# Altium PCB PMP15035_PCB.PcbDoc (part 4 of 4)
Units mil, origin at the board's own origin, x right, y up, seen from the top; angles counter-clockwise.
Board outline 5645 x 4585 mil, 8 copper layers (Top Layer, Signal Layer 1, Signal Layer 2, Signal Layer 3, Signal Layer 4, Signal Layer 5, Signal Layer 6, Bottom Layer), stack 60.9 mil thick; 335 components, 164 nets, 981 pads, 1349 vias.
Unrouted connection lines stored in the file: 46.
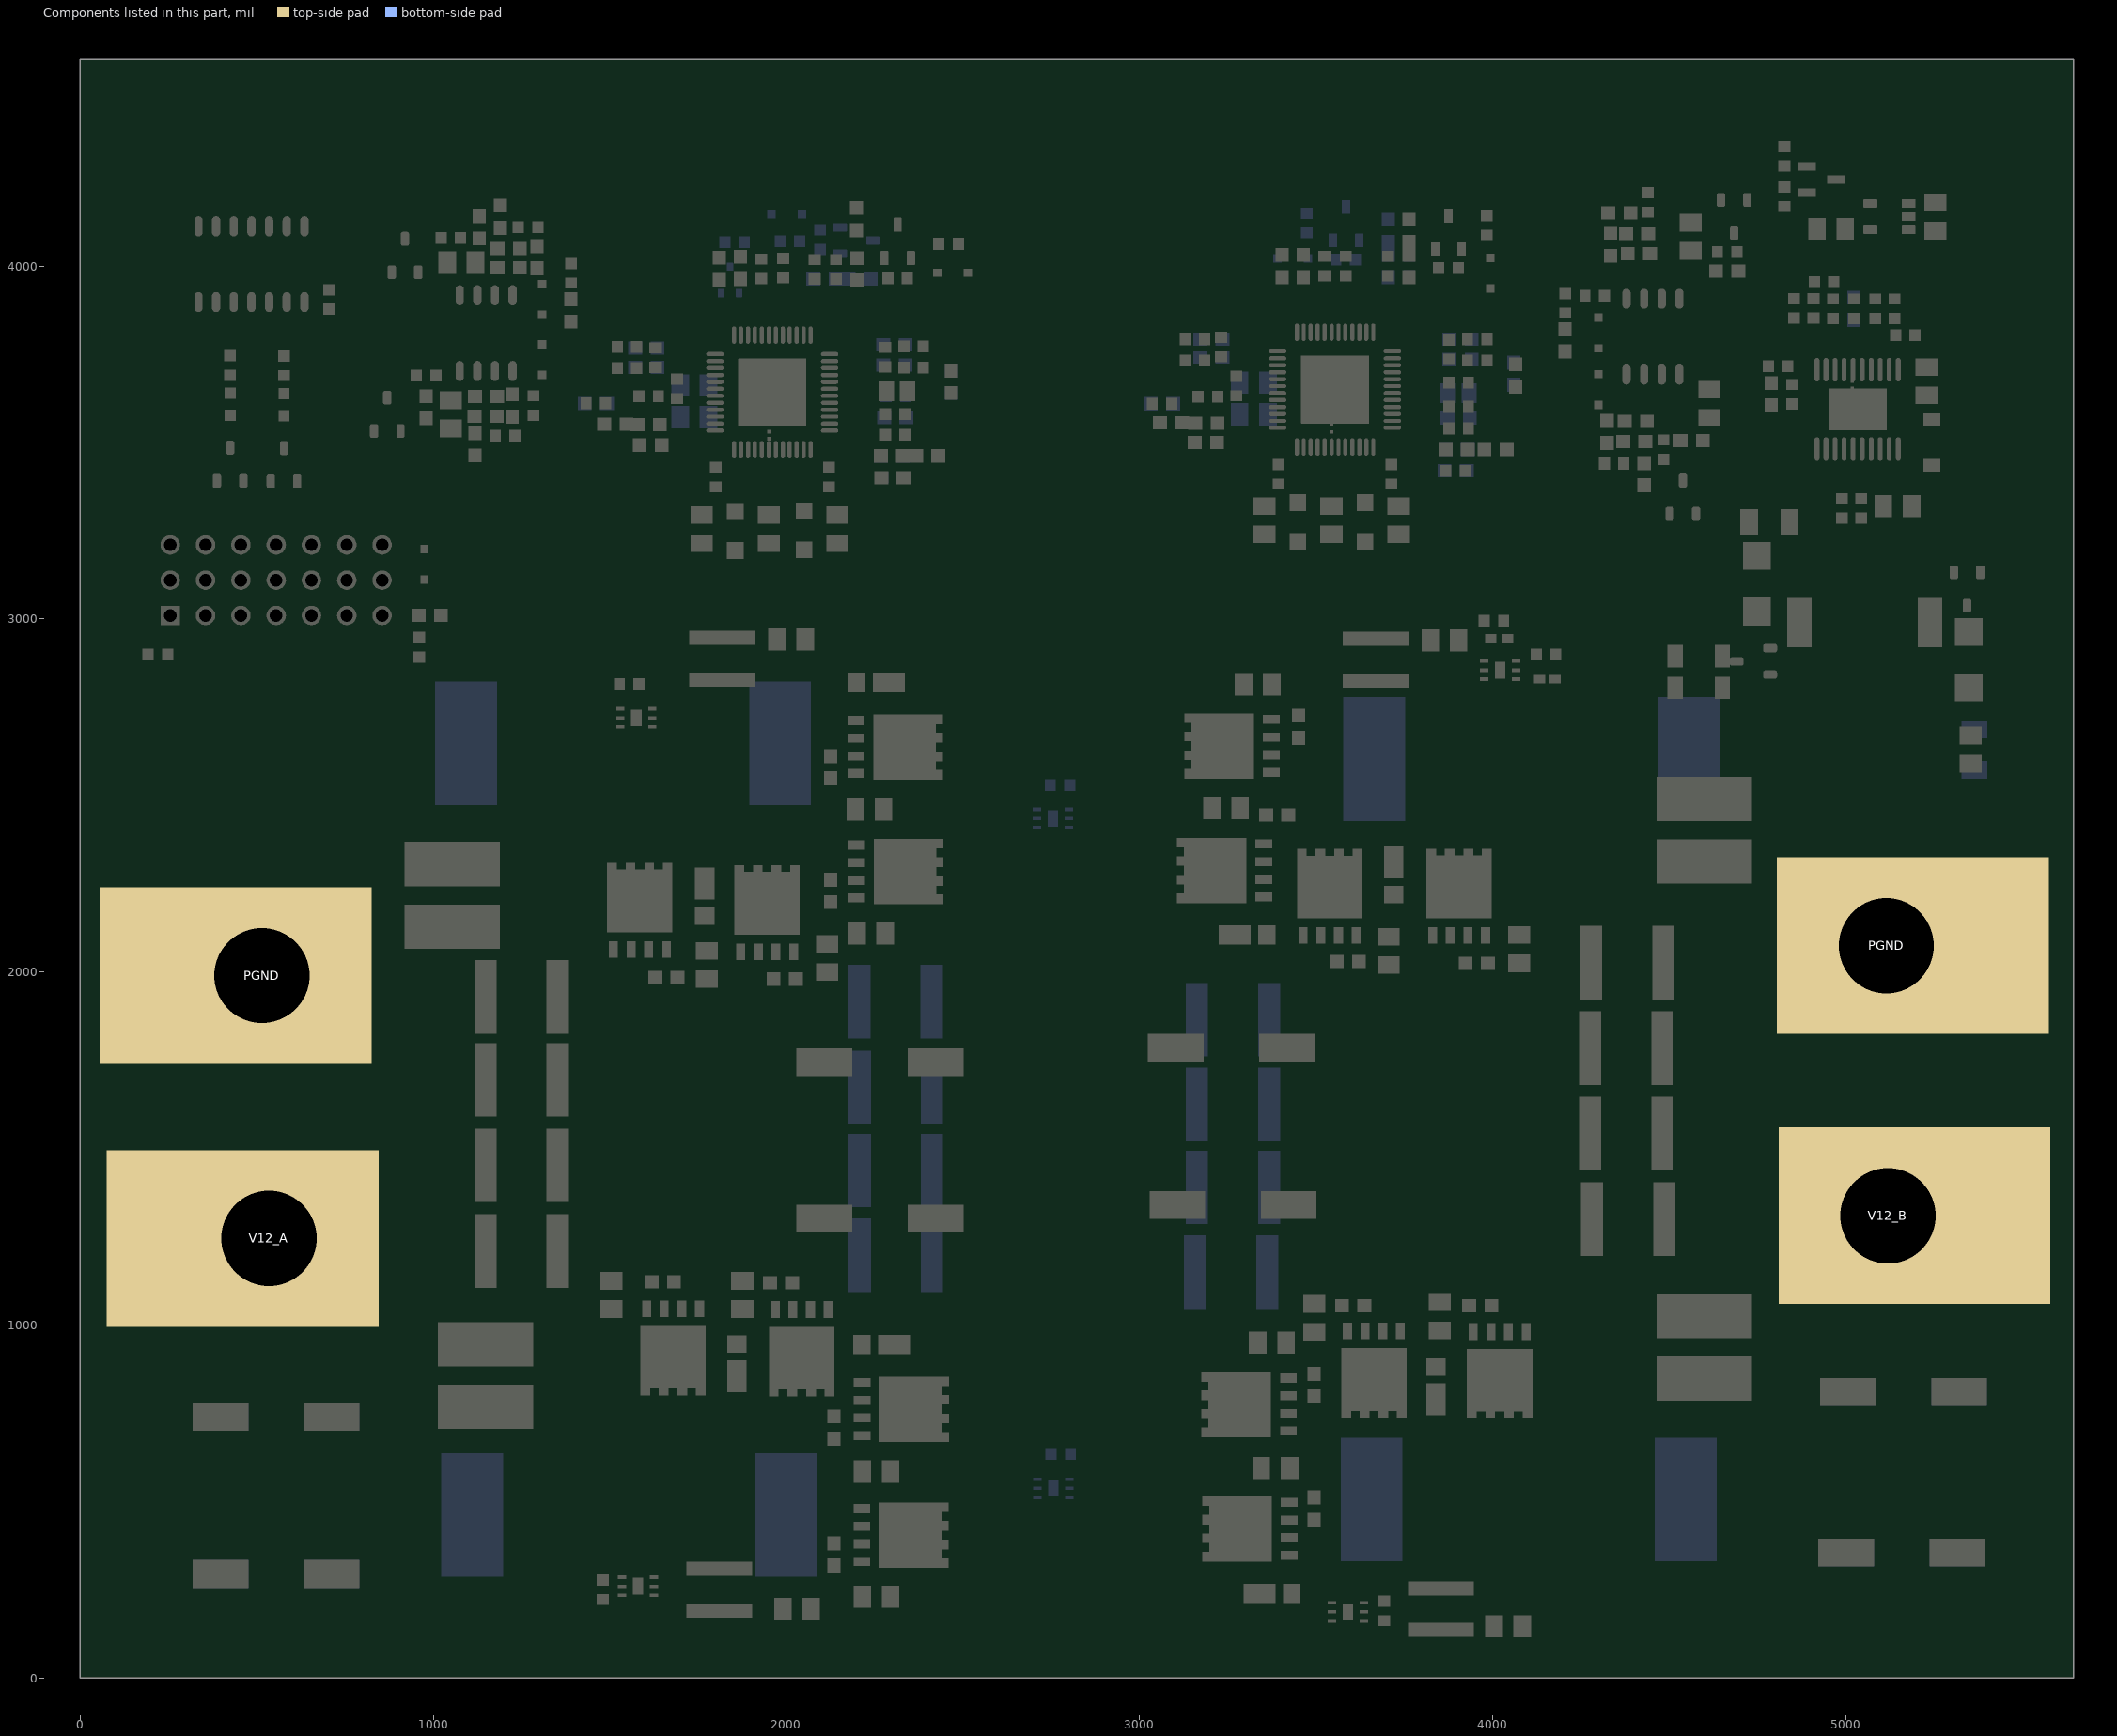
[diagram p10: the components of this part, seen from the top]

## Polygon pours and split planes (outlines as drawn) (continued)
NetL10_2 on Bottom Layer "BOTTOM_LAYER_NETL10_2_P1039" (solid, remove dead copper, pour order 1039): 19 vertices, not listed, extent 4129.88,2410 4739.88,3013.71
NetL11_1 on Bottom Layer "BOTTOM_LAYER_NETL11_1_P1040" (solid, remove dead copper, pour order 1040): 18 vertices, not listed, extent 4127.5,332.5 4745.26,915
NetL9_2 on Bottom Layer "BOTTOM_LAYER_NETL9_2_P1041" (solid, remove dead copper, pour order 1041): 17 vertices, not listed, extent 970,115 1520,718.52
AGND on Bottom Layer "BOTTOM_LAYER_AGND_P022" (solid, remove dead copper, pour order 1036): 2663.26,2583.41 2683.26,2603.41 2829.99,2603.41 2843.26,2590.15 2843.26,2398.26 2828.41,2383.41 2683.26,2383.41 2663.26,2403.41
SW11 on Bottom Layer "BOTTOM_LAYER_SW11_P1046" (solid, remove dead copper, pour order 1046): 25 vertices, not listed, extent 1493.19,2100 2225,2870
SW22 on Bottom Layer "Top Layer-SW226" (solid, remove dead copper, pour order 1043): 46 vertices, not listed, extent 3392.51,210 4115,938.8
SW21 on Bottom Layer "Top Layer-SW216" (solid, remove dead copper, pour order 1044): 28 vertices, not listed, extent 1585,285 2240,1000
SW12 on Bottom Layer "BOTTOM_LAYER_SW12_P1045" (solid, remove dead copper, pour order 1045): 31 vertices, not listed, extent 3325,2070 4005,2849.3
PGND on Top Layer "TOP_LAYER_PGND_P972" (solid, remove dead copper, pour order 972): 5641.25,2.5 5641.25,3706.49 5622.26,3687.5 -2.5,3687.5 -2.5,7.5 5636.25,7.5
AGND on Top Layer "Signal Layer 6-AGND" (solid, remove dead copper, pour order 971): 3364,3534 3706,3534 4090,3150 4495,3150 4940,3665 5643.75,3665 5643.75,4585 0,4585 0,2860 1120,2860 1790,3530 2095,3530 2430,3195 3025,3195
PGND on Top Layer "TOP_LAYER_PGND_P956" (solid, remove dead copper, pour order 956): 5390,310 5235,310 5225,320 5225,480 5260,515 5385,515 5410,490 5410,324.29
PGND on Top Layer "TOP_LAYER_PGND_P955" (solid, remove dead copper, pour order 955): 5245,855 5400,855 5410,845 5410,695 5378.85,663.85 5246.15,663.85 5225,685 5225,840.71
Vmid on Top Layer "Top Layer-Vmid1" (solid, remove dead copper, pour order 970): 3325,911.7 3385,851.7 3385,220 3360,195 2410,195 2235,370 2235,2848.39 2251.61,2865 3200,2865 3325,2740
V12_A on Top Layer "TOP_LAYER_V12_A_P968" (solid, remove dead copper, pour order 968): 1269.68,2130.31 1205,2195 910,2195 870.17,2155.17 870.17,2070 80,2070 80,340 205,215 230,215 390,215 770,215 830,275 830,785 935,890 1269.68,890
PGND on Top Layer "TOP_LAYER_PGND_P949" (solid, remove dead copper, pour order 949): 325,250 310,265 310,410 336.56,436.56 463.44,436.56 485,415 485,265 470,250
PGND on Top Layer "TOP_LAYER_PGND_P950" (solid, remove dead copper, pour order 950): 470,790 485,775 485,630 458.44,603.44 331.56,603.44 310,625 310,775 325,790
PGND on Top Layer "TOP_LAYER_PGND_P948" (solid, remove dead copper, pour order 948): 5245,313.44 5230,328.44 5230,473.44 5256.56,500 5383.44,500 5405,478.44 5405,328.44 5390,313.44
PGND on Top Layer "TOP_LAYER_PGND_P951" (solid, remove dead copper, pour order 951): 5390,865 5405,850 5405,705 5378.44,678.44 5251.56,678.44 5230,700 5230,850 5245,865
SW22 on Top Layer "TOP_LAYER_SW22_P214" (solid, remove dead copper, pour order 964): 46 vertices, not listed, extent 3392.51,210 4115,938.8
SW21 on Top Layer "TOP_LAYER_SW21_P034" (solid, remove dead copper, pour order 965): 28 vertices, not listed, extent 1585,285 2240,1000
AGND on Top Layer "TOP_LAYER_AGND_P028" (solid, remove dead copper, pour order 959): 3968.55,3043.55 4206.16,3043.55 4226.16,3023.55 4226.16,2852.57 4177.14,2803.55 3961.87,2803.55 3950,2815.41 3950,3025
AGND on Top Layer "TOP_LAYER_AGND_P026" (solid, remove dead copper, pour order 952): 1515,2855 1630,2855 1655,2830 1655,2675 1630,2650 1510,2650 1490,2670 1490,2830
AGND on Top Layer "TOP_LAYER_AGND_P020" (solid, remove dead copper, pour order 954): 1484.11,315 1670,315 1690,295 1690,190 1670,170 1475,170 1445,200 1445,282.41
AGND on Top Layer "TOP_LAYER_AGND_P018" (solid, remove dead copper, pour order 947): 3535,255 3700,255 3725,230 3725,150 3690,115 3550,115 3510,155 3510,230
NetD8_2 on Top Layer "TOP_LAYER_NETD8_2_P004" (solid, remove dead copper, pour order 953): 5180,3065 5375,3065 5395,3045 5395,2925 5385,2915 5180,2915 5170,2925 5170,3055
NetC21_1 on Top Layer "TOP_LAYER_NETC21_1_P958" (solid, remove dead copper, pour order 958): 4700,3095 4710,3105 4910,3105 4945,3070 4945,2930 4900,2885 4770,2885 4700,2955
NetL9_2 on Top Layer "TOP_LAYER_NETL9_2_P961" (solid, remove dead copper, pour order 961): 1520,375 1435,290 1435,165 1390,120 1060,120 975,205 975,794.62 1020.86,832.84 1287.16,832.84 1295,825 1295,720 1402.23,612.76 1472.24,612.76 1520,565
NetL8_1 on Top Layer "TOP_LAYER_NETL8_1_P963" (solid, remove dead copper, pour order 963): 891.49,2269.85 918.19,2243.15 1159.91,2243.15 1228.28,2175 1430,2175 1515,2260 1515,2755 1435,2835 1023.32,2835 1000,2814.6 1000,2480 891.49,2371.49
SW11 on Top Layer "TOP_LAYER_SW11_P967" (solid, remove dead copper, pour order 967): 34 vertices, not listed, extent 1493.19,2100 2225,2870
NetL11_1 on Top Layer "TOP_LAYER_NETL11_1_P962" (solid, remove dead copper, pour order 962): 4150,705 4125,680 4125,660 4125,495 4305,315 4635,315 4745,425 4745,905 4735,915 4255,915 4220,880 4220,719.25 4209.11,705
NetL10_2 on Top Layer "TOP_LAYER_NETL10_2_P960" (solid, remove dead copper, pour order 960): 17 vertices, not listed, extent 4132.96,2431.35 4742.96,3005
SW12 on Top Layer "TOP_LAYER_SW12_P966" (solid, remove dead copper, pour order 966): 31 vertices, not listed, extent 3325,2070 4005,2849.3
V12_B on Top Layer "TOP_LAYER_V12_B_P969" (solid, remove dead copper, pour order 969): 4796.5,960 4776.5,980 4740,980 4740,960 4420,960 4420,2331.92 4461.66,2373.58 5613.91,2373.58 5613.91,755 5613.91,380 5483.91,250 4980,250 4858.91,371.09 4858.91,901.09 4800,960
VCC1 on Top Layer "TOP_LAYER_VCC1_P957" (solid, remove dead copper, pour order 957): 5314.3,2890 5400.89,2890 5430,2860.88 5430,2647.82 5401.45,2619.28 5310.07,2619.28 5279.85,2649.5 5279.85,2857.92
PGND on Signal Layer 2 "SIGNAL_LAYER_2_PGND_P991" (solid, remove dead copper, pour order 991): 5643.75,0 5643.75,3703.99 5624.76,3685 0,3685 0,5 5638.75,5
AGND on Signal Layer 2 "Signal Layer 6-AGND2" (solid, remove dead copper, pour order 990): 3364,3534 3706,3534 4090,3150 4495,3150 4940,3665 5643.75,3665 5643.75,4585 0,4585 0,2860 1120,2860 1790,3530 2095,3530 2430,3195 3025,3195
Vmid on Signal Layer 2 "Top Layer-Vmid" (solid, remove dead copper, pour order 989): 3325,911.7 3385,851.7 3385,220 3360,195 2410,195 2235,370 2235,2848.39 2251.61,2865 3200,2865 3325,2740
V12_A on Signal Layer 2 "SIGNAL_LAYER_2_V12_A_P987" (solid, remove dead copper, pour order 987): 1269.68,2130.31 1205,2195 910,2195 870.17,2155.17 870.17,2070 80,2070 80,340 205,215 230,215 390,215 770,215 830,275 830,725 990,885 1269.68,885
V12_B on Signal Layer 2 "SIGNAL_LAYER_2_V12_B_P988" (solid, remove dead copper, pour order 988): 5613.91,755 5613.91,380 5483.91,250 4980,250 4858.91,371.09 4858.91,880 4809.46,929.45 4455.55,929.45 4420,965 4420,2335 4485,2400 5613.91,2400
NetL11_1 on Signal Layer 2 "SIGNAL_LAYER_2_NETL11_1_P979" (solid, remove dead copper, pour order 979): 4727.67,769.28 4577.67,919.28 4257.67,919.28 4212.67,874.28 4212.67,549.28 4357.67,404.28 4472.67,404.28 4727.67,659.28
NetL10_2 on Signal Layer 2 "SIGNAL_LAYER_2_NETL10_2_P980" (solid, remove dead copper, pour order 980): 4730.39,2544.14 4660.39,2474.14 4350.39,2474.14 4174.45,2650.08 4174.45,2933.2 4255.39,3014.14 4468.25,3014.14 4730.39,2752
NetL9_2 on Signal Layer 2 "SIGNAL_LAYER_2_NETL9_2_P981" (solid, remove dead copper, pour order 981): 1180,725 975,520 975,495 975,200 1075,100 1380,100 1475.47,195.47 1475.47,606.25 1356.72,725
NetL8_1 on Signal Layer 2 "SIGNAL_LAYER_2_NETL8_1_P982" (solid, remove dead copper, pour order 982): 994.25,2360.75 1180,2175 1430,2175 1514.57,2259.57 1514.57,2755.43 1470,2800 1219.29,2800 994.25,2603.1
SW11 on Signal Layer 2 "SIGNAL_LAYER_2_SW11_P986" (solid, remove dead copper, pour order 986): 25 vertices, not listed, extent 1493.19,2100 2225,2870
SW22 on Signal Layer 2 "Top Layer-SW221" (solid, remove dead copper, pour order 983): 46 vertices, not listed, extent 3392.51,210 4115,938.8
SW21 on Signal Layer 2 "Top Layer-SW211" (solid, remove dead copper, pour order 984): 28 vertices, not listed, extent 1585,285 2240,1000
SW12 on Signal Layer 2 "SIGNAL_LAYER_2_SW12_P985" (solid, remove dead copper, pour order 985): 31 vertices, not listed, extent 3325,2070 4005,2849.3
PGND on Signal Layer 3 "SIGNAL_LAYER_3_PGND_P1004" (solid, remove dead copper, pour order 1004): 5643.75,0 5643.75,3703.99 5624.76,3685 0,3685 0,5 5638.75,5
AGND on Signal Layer 3 "Signal Layer 6-AGND3" (solid, remove dead copper, pour order 1003): 3364,3534 3706,3534 4090,3150 4495,3150 4940,3665 5643.75,3665 5643.75,4585 0,4585 0,2860 1120,2860 1790,3530 2095,3530 2430,3195 3025,3195
Vmid on Signal Layer 3 "Top Layer-Vmid2" (solid, remove dead copper, pour order 1002): 3325,911.7 3385,851.7 3385,220 3360,195 2410,195 2235,370 2235,2848.39 2251.61,2865 3200,2865 3325,2740
V12_A on Signal Layer 3 "SIGNAL_LAYER_3_V12_A_P1000" (solid, remove dead copper, pour order 1000): 1269.68,2130.31 1205,2195 910,2195 870.17,2155.17 870.17,2070 80,2070 80,340 205,215 230,215 390,215 770,215 830,275 830,725 990,885 1269.68,885
NetL8_1 on Signal Layer 3 "SIGNAL_LAYER_3_NETL8_1_P995" (solid, remove dead copper, pour order 995): 994.25,2360.75 1180,2175 1430,2175 1514.57,2259.57 1514.57,2755.43 1470,2800 1219.29,2800 994.25,2603.1
NetL11_1 on Signal Layer 3 "SIGNAL_LAYER_3_NETL11_1_P992" (solid, remove dead copper, pour order 992): 4735.39,769.14 4585.39,919.14 4265.39,919.14 4220.39,874.14 4220.39,549.14 4365.39,404.14 4480.39,404.14 4735.39,659.14
NetL9_2 on Signal Layer 3 "SIGNAL_LAYER_3_NETL9_2_P994" (solid, remove dead copper, pour order 994): 1180,725 975,520 975,495 975,200 1075,100 1380,100 1475.47,195.47 1475.47,604.53 1355,725
NetL10_2 on Signal Layer 3 "SIGNAL_LAYER_3_NETL10_2_P993" (solid, remove dead copper, pour order 993): 4740.39,2549.14 4670.39,2479.14 4360.39,2479.14 4184.45,2655.08 4184.45,2938.2 4265.39,3019.14 4478.25,3019.14 4740.39,2757
V12_B on Signal Layer 3 "SIGNAL_LAYER_3_V12_B_P1001" (solid, remove dead copper, pour order 1001): 5613.91,755 5613.91,380 5483.91,250 4980,250 4858.91,371.09 4858.91,880 4809.46,929.45 4455.55,929.45 4420,965 4420,2331.92 4488.08,2400 5613.91,2400
SW11 on Signal Layer 3 "SIGNAL_LAYER_3_SW11_P999" (solid, remove dead copper, pour order 999): 25 vertices, not listed, extent 1493.19,2100 2225,2870
SW22 on Signal Layer 3 "Top Layer-SW222" (solid, remove dead copper, pour order 996): 46 vertices, not listed, extent 3392.51,210 4115,938.8
SW21 on Signal Layer 3 "Top Layer-SW212" (solid, remove dead copper, pour order 997): 28 vertices, not listed, extent 1585,285 2240,1000
SW12 on Signal Layer 3 "SIGNAL_LAYER_3_SW12_P998" (solid, remove dead copper, pour order 998): 31 vertices, not listed, extent 3325,2070 4005,2849.3
PGND on Signal Layer 5 "SIGNAL_LAYER_5_PGND_P1023" (solid, remove dead copper, pour order 1023): 5643.75,0 5643.75,3703.99 5624.76,3685 0,3685 0,5 5638.75,5
AGND on Signal Layer 5 "Signal Layer 6-AGND5" (solid, remove dead copper, pour order 1022): 3364,3534 3706,3534 4090,3150 4495,3150 4940,3665 5643.75,3665 5643.75,4585 0,4585 0,2860 1120,2860 1790,3530 2095,3530 2430,3195 3025,3195
Vmid on Signal Layer 5 "Top Layer-Vmid3" (solid, remove dead copper, pour order 1021): 3325,911.7 3385,851.7 3385,220 3360,195 2410,195 2235,370 2235,2848.39 2251.61,2865 3200,2865 3325,2740
V12_A on Signal Layer 5 "SIGNAL_LAYER_5_V12_A_P1019" (solid, remove dead copper, pour order 1019): 1269.68,2130.31 1205,2195 910,2195 870.17,2155.17 870.17,2070 80,2070 80,340 205,215 230,215 390,215 770,215 830,275 830,725 990,885 1269.68,885
NetL8_1 on Signal Layer 5 "SIGNAL_LAYER_5_NETL8_1_P1014" (solid, remove dead copper, pour order 1014): 994.25,2360.75 1180,2175 1430,2175 1514.57,2259.57 1514.57,2755.43 1470,2800 1219.29,2800 994.25,2603.1
NetL11_1 on Signal Layer 5 "SIGNAL_LAYER_5_NETL11_1_P1011" (solid, remove dead copper, pour order 1011): 4730.39,770.86 4580.39,920.86 4260.39,920.86 4215.39,875.86 4215.39,550.86 4360.39,405.86 4475.39,405.86 4730.39,660.86
NetL9_2 on Signal Layer 5 "SIGNAL_LAYER_5_NETL9_2_P1013" (solid, remove dead copper, pour order 1013): 1180,725 975,520 975,495 975,200 1075,100 1380,100 1475.47,195.47 1475.47,618.95 1369.42,725
NetL10_2 on Signal Layer 5 "SIGNAL_LAYER_5_NETL10_2_P1012" (solid, remove dead copper, pour order 1012): 4744.07,2543.41 4674.07,2473.41 4364.07,2473.41 4188.14,2649.34 4188.14,2932.47 4269.07,3013.41 4481.94,3013.41 4744.07,2751.26
V12_B on Signal Layer 5 "SIGNAL_LAYER_5_V12_B_P1020" (solid, remove dead copper, pour order 1020): 5613.91,755 5613.91,380 5483.91,250 4980,250 4858.91,371.09 4858.91,880 4809.46,929.45 4455.55,929.45 4420,965 4420,2331.92 4488.08,2400 5613.91,2400
SW11 on Signal Layer 5 "SIGNAL_LAYER_5_SW11_P1018" (solid, remove dead copper, pour order 1018): 25 vertices, not listed, extent 1493.19,2100 2225,2870
SW22 on Signal Layer 5 "Top Layer-SW224" (solid, remove dead copper, pour order 1015): 46 vertices, not listed, extent 3392.51,210 4115,938.8
SW21 on Signal Layer 5 "Top Layer-SW214" (solid, remove dead copper, pour order 1016): 28 vertices, not listed, extent 1585,285 2240,1000
SW12 on Signal Layer 5 "SIGNAL_LAYER_5_SW12_P1017" (solid, remove dead copper, pour order 1017): 31 vertices, not listed, extent 3325,2070 4005,2849.3
PGND on Signal Layer 6 "SIGNAL_LAYER_6_PGND_P1029" (solid, remove dead copper, pour order 1029): 5643.75,0 5643.75,3703.99 5624.76,3685 0,3685 0,5 5638.75,5
AGND on Signal Layer 6 "Top Layer-AGND5" (solid, remove dead copper, pour order 1028): 3364,3534 3706,3534 4090,3150 4495,3150 4940,3665 5643.75,3665 5643.75,4585 0,4585 0,2860 1120,2860 1790,3530 2095,3530 2430,3195 3025,3195
SW11 on Signal Layer 6 "SIGNAL_LAYER_6_SW11_P1027" (solid, remove dead copper, pour order 1027): 25 vertices, not listed, extent 1493.19,2100 2225,2870
SW22 on Signal Layer 6 "Top Layer-SW225" (solid, remove dead copper, pour order 1024): 46 vertices, not listed, extent 3392.51,210 4115,938.8
SW21 on Signal Layer 6 "Top Layer-SW215" (solid, remove dead copper, pour order 1025): 28 vertices, not listed, extent 1585,285 2240,1000
SW12 on Signal Layer 6 "SIGNAL_LAYER_6_SW12_P1026" (solid, remove dead copper, pour order 1026): 31 vertices, not listed, extent 3325,2070 4005,2849.3
PGND on Signal Layer 1 "SIGNAL_LAYER_1_PGND_P978" (solid, remove dead copper, pour order 978): 5643.75,0 5643.75,3703.99 5624.76,3685 0,3685 0,5 5638.75,5
AGND on Signal Layer 1 "Signal Layer 6-AGND1" (solid, remove dead copper, pour order 977): 3364,3534 3706,3534 4090,3150 4495,3150 4940,3665 5643.75,3665 5643.75,4585 0,4585 0,2860 1120,2860 1790,3530 2095,3530 2430,3195 3025,3195
SW11 on Signal Layer 1 "SIGNAL_LAYER_1_SW11_P976" (solid, remove dead copper, pour order 976): 25 vertices, not listed, extent 1493.19,2100 2225,2870
SW22 on Signal Layer 1 "Top Layer-SW22" (solid, remove dead copper, pour order 973): 46 vertices, not listed, extent 3392.51,210 4115,938.8
SW21 on Signal Layer 1 "Top Layer-SW21" (solid, remove dead copper, pour order 974): 28 vertices, not listed, extent 1585,285 2240,1000
SW12 on Signal Layer 1 "SIGNAL_LAYER_1_SW12_P975" (solid, remove dead copper, pour order 975): 31 vertices, not listed, extent 3325,2070 4005,2849.3
PGND on Signal Layer 4 "SIGNAL_LAYER_4_PGND_P1010" (solid, remove dead copper, pour order 1010): 5643.75,0 5643.75,3703.99 5624.76,3685 0,3685 0,5 5638.75,5
AGND on Signal Layer 4 "Bottom Layer-AGND" (solid, remove dead copper, pour order 1009): 3364,3534 3706,3534 4090,3150 4495,3150 4940,3665 5643.75,3665 5643.75,4585 0,4585 0,2860 1120,2860 1790,3530 2095,3530 2430,3195 3025,3195
SW11 on Signal Layer 4 "SIGNAL_LAYER_4_SW11_P1008" (solid, remove dead copper, pour order 1008): 25 vertices, not listed, extent 1493.19,2100 2225,2870
SW22 on Signal Layer 4 "Top Layer-SW223" (solid, remove dead copper, pour order 1005): 46 vertices, not listed, extent 3392.51,210 4115,938.8
SW21 on Signal Layer 4 "Top Layer-SW213" (solid, remove dead copper, pour order 1006): 28 vertices, not listed, extent 1585,285 2240,1000
SW12 on Signal Layer 4 "SIGNAL_LAYER_4_SW12_P1007" (solid, remove dead copper, pour order 1007): 31 vertices, not listed, extent 3325,2070 4005,2849.3

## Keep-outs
Keep-Out Layer:
  the board outline again, w8
  text ".Layer_Name" at -1078,-1628.49 h40

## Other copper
Top Layer:
  pour cut-out: 3425.03,3764.47 3448.35,3787.8 3659.14,3787.8 3688.75,3758.19 3688.75,3523.38 3677.58,3512.2 3427.86,3512.2 3418.75,3521.32 3418.75,3756.41
  pour cut-out: 1822.66,3767.66 1835,3780 2074.33,3780 2092.39,3761.94 2092.39,3516.42 2080.68,3504.71 1836.23,3504.71 1822.66,3520 1822.66,3523.61
  pour cut-out: 4919.8,3670 5138.75,3670 5153.75,3655 5153.75,3525 5138.75,3510 4918.55,3510 4903.83,3524.73 4903.83,3657.14
  text ".Layer_Name" at -1078,-1628.49 h40
Signal Layer 1:
  text "'.Layer_Name'" at -1080,-1625 h72.83
Signal Layer 2:
  pour cut-out: 927.13,2200 927.13,823.13 967.13,863.13 967.13,2187.87 955,2200
  pour cut-out: 4748.32,955 4749.13,954.19 4749.13,930 4770.87,930 4770.87,955
  pour cut-out: 4485,1222.87 4485,1221.62 4778.19,928.43 4785,935.23 4785,965 4527.13,1222.87
  pour cut-out: 4511.94,1222.87 4485,1222.87 4485,2405 4511.94,2405
  pour cut-out: 4475,2470 4460,2470 4455,2475 4455,3021.55 4481.94,3021.55 4481.94,2476.94
  pour cut-out: 4473.45,2474.14 4473.45,3021.55 4470,3025 4468.25,3023.25 4468.25,2468.37 4468.75,2467.87 4468.75,2469.43
  text "'.Layer_Name'" at -1085,-1630 h72.83
Signal Layer 3:
  text "'.Layer_Name'" at -1075,-1635 h72.83
Signal Layer 4:
  text "'.Layer_Name'" at -1080,-1640 h72.83
Signal Layer 5:
  text "'.Layer_Name'" at -1080,-1645 h72.83
Signal Layer 6:
  text "'.Layer_Name'" at -1070,-1635 h72.83
Bottom Layer:
  text ".Layer_Name" at -1078,-1628.49 h40

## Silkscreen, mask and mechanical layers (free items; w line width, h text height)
Top Overlay:
  lines w7: 4390,3400 4397.63,3407.63 4397.63,3413.51 4397.63,3454.66 4400,3457.04 4400,3475 ; 4400,3475 4405,3470 4395,3470 4400,3475
  text "A to B" at 374.63,3270.37 h72.83
  text "LOW" at 35,3200 h72.83
  text "HIGH" at 35,2985 h72.83
  text "EN1" at 275,2760 h72.83 r90
  text "EN2" at 370,2755 h72.83 r90
  text "B to A" at 470,2755 h72.83 r90
  text "UVLO" at 890,2755 h72.83 r90
  text "SYNCIN" at 575,2700 h72.83 r90
  text ".Layer_Name" at -1078,-1628.49 h40
Bottom Overlay:
  text ".Layer_Name" at -1078,-1628.49 h40
Top Paste:
  text ".Layer_Name" at -1078,-1628.49 h40
Bottom Paste:
  text ".Layer_Name" at -1078,-1628.49 h40
Top Solder:
  text ".Layer_Name" at -1078,-1628.49 h40
  text ".Layer_Name" at -1078,-1628.49 h40
Bottom Solder:
  text ".Layer_Name" at -1078,-1628.49 h40
Drill Guide:
  text ".Layer_Name" at -1078,-1628.49 h40
M1 Board Outline:
  the board outline again, w10
  text ".Layer_Name" at -1078,-1628.49 h40
M2 Board Dimensions:
  lines w7: 0,-85 0,165 ; 5643.75,-190 5643.75,60
  text ".Layer_Name" at -1078,-1628.49 h40
M3 3D STEP Top:
  text ".Layer_Name" at -1078,-1628.49 h40
M4 3D STEP Bottom:
  text ".Layer_Name" at -1078,-1628.49 h40
M5 Assembly Top:
  lines w10: -1947,-1700.17 4653,-1700.17 ; -1947,-1496.83 4655,-1496.83 ; -1947,-1293.5 -1947,-1903.5 2058,-1903.5 4655,-1903.5 4655,-1293.5 -1946.5,-1293.5 -1946.5,-1903.5 -371,-1903.5 ; 518,-1903.5 518,-1293.5 ; 1785,-1496.83 1785,-1293.5 ; 2625,-1496.83 2625,-1293.5 ; 3247,-1910 3247,-1707.17
  text "COMPONENTS MARKED 'DNP' SHOULD NOT BE POPULATED." at 563.5,151.5 h40
  text "ASSEMBLY VARIANT:" at 563,36 h40
  text ".VariantName" at 1599,36 h40
  text "PCB VIEWED FROM TOP SIDE" at -1883.5,-1425.67 h40
  text "BOARD #:" at 593,-1425.67 h40
  text ".PRJ_Number" at 1138.5,-1425.67 h40
  text "REV:" at 1983,-1425.67 h40
  text ".PCB_Rev" at 2274.5,-1425.67 h40
  text "SVN REV:" at 2821,-1425.67 h40
  text ".VersionControl_RevNumber" at 3327,-1425.67 h40
  text "TID #:" at 593,-1629 h40
  text ".TID" at 1138.5,-1629 h40
  text "PLOT NAME =" at -1883.5,-1834.34 h40
  text ".plot_File_Name" at -1078,-1834.34 h40
  text "GENERATED    :" at 595,-1834.34 h40
  text ".Print_Date" at 1464.5,-1834.34 h40
  text ".Print_Time" at 2193.5,-1834.34 h40
  text "TEXAS INSTRUMENTS" at 3458,-1834.34 h40
M6 Assembly Bottom:
  lines w10: -1947.5,-1497.33 4654.5,-1497.33 ; -1945.5,-1700.67 4654.5,-1700.67 ; -539.5,-1910.5 -539.5,-1707.67 ; 82.5,-1497.33 82.5,-1294 ; 922.5,-1497.33 922.5,-1294 ; 2189.5,-1904 2189.5,-1294 ; 3078.5,-1904 4654,-1904 4654,-1294 -1947.5,-1294 -1947.5,-1904 649.5,-1904 4654.5,-1904 4654.5,-1294
  text "COMPONENTS MARKED 'DNP' SHOULD NOT BE POPULATED." at 5890.75,162 h40
  text ".VariantName" at 4846.75,46 h40
  text "ASSEMBLY VARIANT:" at 6300,-45 h40
  text ".VersionControl_RevNumber" at -619.5,-1426.17 h40
  text "SVN REV:" at -113.5,-1426.17 h40
  text ".PCB_Rev" at 433,-1426.17 h40
  text "REV:" at 724.5,-1426.17 h40
  text ".PRJ_Number" at 1569,-1426.17 h40
  text "BOARD #:" at 2114.5,-1426.17 h40
  text "PCB VIEWED FROM BOTTOM SIDE" at 4591,-1426.17 h40
  text ".TID" at 1569,-1629.5 h40
  text "TID #:" at 2114.5,-1629.5 h40
  text "TEXAS INSTRUMENTS" at -750.5,-1834.84 h40
  text ".Print_Time" at 514,-1834.84 h40
  text ".Print_Date" at 1243,-1834.84 h40
  text "GENERATED    :" at 2112.5,-1834.84 h40
  text ".plot_File_Name" at 3785.5,-1834.84 h40
  text "PLOT NAME =" at 4591,-1834.84 h40
M9 Title Sheet:
  drawing of 57 lines, arcs and shapes, not listed
  text "1" at -915.16,7266.5 h40
  text "2" at 1580.5,7266.5 h40
  text "3" at 4069.84,7266.5 h40
  text "4" at 6576.51,7266.5 h40
  text "5" at 9075.5,7266.5 h40
  text "6" at 11580.5,7266.5 h40
  text "A" at -2071.5,6123.5 h40
  text "A" at 12728.5,6123.5 h40
  text "B" at -2071.5,3743.5 h40
  text "B" at 12728.5,3743.5 h40
  text "C" at -2071.5,1368.5 h40
  text "C" at 12728.5,1368.5 h40
  text "PROJECT TITLE:" at 9688.5,-492.5 h40
  text ".PRJ_Title" at 9738.5,-625.83 h40
  text "DESIGNED FOR:" at 9688.5,-793.5 h40
  text ".PRJ_Customer" at 9738.5,-933.5 h40
  text "D" at -2071.5,-1001.5 h40
  text "D" at 12728.5,-1001.5 h40
  text "FILE NAME:" at 9688.5,-1093.5 h40
  text ".PCB_File_Name_No_Path" at 9738.5,-1213.5 h40
  text "Texas Instruments (TI) and/or its licensors do not warrant the accuracy or completeness of this specification" at 4719,-1375.34 h40
  text "ENGINEER:" at 9688.5,-1383.5 h40
  text "LAYOUT BY:" at 11193.5,-1383.5 h40
  text "or any information contained therein. TI and/or its licensors do not warrant that this design will meet" at 4674.01,-1488 h40
  text ".PRJ_Engineer" at 9738.5,-1538.49 h40
  text ".PCB_Layout" at 11244,-1538.49 h40
  text "the specifications, will be suitable for your application or fit for any particular purpose, or will operate in" at 4674.01,-1600.67 h40
  text ".Layer_Name" at -1078,-1628.49 h40
  text "ALTIUM DESIGNER VERSION:" at 11193.5,-1693.5 h40
  text "an implementation. TI and/or its licensors do not warrant that the design is production worthy. You should" at 4674.01,-1713.33 h40
  text "completely validate and test your design implementation to confirm the system functionality for your application." at 4719,-1826 h40
  text ".print_Scale" at 9738.5,-1826.83 h40
  text ".Application_BuildNumber" at 11244,-1826.83 h40
  text "1" at -915.16,-2033.5 h40
  text "2" at 1580.5,-2033.5 h40
  text "3" at 4069.84,-2033.5 h40
  text "4" at 6576.51,-2033.5 h40
  text "5" at 9075.5,-2033.5 h40
  text "6" at 11580.5,-2033.5 h40
M10 Fab Notes:
  drawing of 189 lines, arcs and shapes, not listed
  text "DESIGN INFORMATION" at 10727.02,5586.17 h40
  text "MIN. TRACK WIDTH:" at 10082.46,5454.05 h40
  text "8" at 11178.7,5454.05 h40
  text "MIL" at 11333.46,5454.05 h40
  text "MIN. CLEARANCE:" at 10082.46,5329.92 h40
  text "0.2" at 11118.7,5329.93 h40
  text "mm" at 11333.46,5329.92 h40
  text "MIN. VIA PAD SIZE:" at 10082.46,5205.8 h40
  text "24" at 11148.71,5205.8 h40
  text "MIL" at 11333.46,5205.8 h40
  text "0.05mm (2MIL)" at 10777.46,5075.9 h40
  text "MINIMUM ANNULAR RING" at 9753.23,5067.67 h40
  text "EXTERNAL" at 11485.46,5067.67 h40
  text "PER" at 9953.23,4957.55 h40
  text "IPC-D-275 CLASS 2 LEVEL C" at 10173.23,4957.54 h40
  text "MIL, HOLES" at 11661.46,4857.07 h40
  text "+/-" at 11269,4848.48 h40
  text "+/-" at 12123,4848.48 h40
  text "REGISTRATION TOLERANCES:" at 9753.23,4847.42 h40
  text "METAL" at 10953,4847.42 h40
  text "5" at 11529.2,4847.42 h40
  text "3" at 12362.2,4847.42 h40
  text "MIL" at 12478.46,4847.42 h40
  text "HOLE SIZE TOLERANCE (UNLESS OTHERWISE SPECIFIED):" at 9753.23,4749.1 h40
  text "+/-" at 12123,4746.23 h40
  text "3" at 12362.2,4745.17 h40
  text "MIL" at 12478.46,4745.17 h40
  text "MATERIAL:" at 9678.46,4607.52 h40
  text "FR-4 High Tg" at 10664.9,4479 h40
  text "X" at 10520.46,4471.01 h40
  text "FR-408" at 10099.46,4466.49 h40
  text "OTHER" at 11587.46,4466.49 h40
  text "62 MIL (1.6mm) +/-10%" at 10419.56,4323.46 h40
  text "X" at 10299.46,4321.01 h40
  text "THICKNESS:" at 9753.23,4315.24 h40
  text "OTHER" at 11704.46,4315.24 h40
  text "TOLERANCE:" at 9753.23,4176.92 h40
  text "X" at 10601.46,4176.92 h40
  text "ANSI IPC-6012 TYPE 3 CLASS 2" at 10779.48,4176.92 h40
  text "OTHER +/-" at 10779.46,4032.73 h40
  text "BOW & TWIST:" at 9753.23,3887.54 h40
  text "X" at 10601.46,3887.54 h40
  text "ANSI IPC-6012 TYPE 3 CLASS 2" at 10779.48,3887.54 h40
  text "OTHER +/-" at 10779.46,3740.85 h40
  text "DRILLING:" at 9678.46,3610.23 h40
  text "NC_DRILL FILES" at 11439.46,3505.04 h40
  text "REFERENCE:" at 9753.23,3501.1 h40
  text "X" at 10410.46,3501.01 h40
  text "AS SHOWN" at 10588.46,3501.1 h40
  text "X" at 11311.46,3501.1 h40
  text "OTHER" at 11737.46,3358.85 h40
  text "PTH COPPER THICKNESS:" at 9752.91,3355.32 h40
  text "X" at 10892.14,3355.32 h40
  text "20-30 um" at 11020.14,3355.32 h40
  text "BOARD FINISH:" at 9678.46,3207.73 h40
  text "SILKSCREEN:" at 9833.68,3097.6 h40
  text "X" at 10791.46,3097.6 h40
  text "TOP" at 10908.46,3097.6 h40
  text "X" at 11301.46,3097.6 h40
  text "BOTTOM" at 11419.46,3097.6 h40
  text "SILKSCREEN COLOR:" at 9833.68,2942.41 h40
  text "X" at 10790.46,2942.41 h40
  text "WHITE" at 10908.46,2942.41 h40
  text "OTHER" at 11419.46,2942.41 h40
  text "X" at 10921.46,2798.96 h40
  text "GREEN" at 11039.46,2798.96 h40
  text "OTHER" at 11657.46,2798.96 h40
  text "SOLDER RESIST COLOR:" at 9833.68,2792.1 h40
  text "X" at 10921.46,2644.71 h40
  text "MATTE" at 11039.46,2644.71 h40
  text "SEMI-GLOSS" at 11657,2644.07 h40
  text "IMMERSION GOLD (ENIG)" at 10739.46,2471.94 h40
  text "ENEPIG" at 12077,2464.72 h40
  text "SURFACE FINISH:" at 9678.46,2463.72 h40
  text "X" at 9855,2335 h40
  text "IMM. TIN/SILVER OR EQUIV" at 10008,2326.4 h40
  text "OTHER" at 11439.46,2322.47 h40
  text "X" at 10565,2175 h40
  text "ARRAY/PANEL:" at 9678.46,2167.09 h40
  text "CUT AND TRIM PER M1 BOARD OUTLINE" at 10739.46,2158.87 h40
  text "N.C. ROUTE" at 10739.46,2022.9 h40
  text "V. SCORE" at 11605.46,2022.9 h40
  text "CERTIFICATION:" at 9678.46,1893.77 h40
  text "MATERIALS AND WORKMANSHIP FOR ALL PCBS" at 10403.46,1893.77 h40
  text "TO MEET OR EXCEED THE REQUIREMENTS OF:" at 10403.46,1799.71 h40
  text "X" at 10040.97,1671.08 h40
  text "ANSI IPC-A-600F CLASS ->" at 10168.96,1671.08 h40
  text "X" at 11816.97,1671.08 h40
  text "2" at 11926.96,1671.08 h40
  text "1" at 11611.96,1669.58 h40
  text "3" at 12280.96,1669.58 h40
  text "X" at 10852.97,1523.39 h40
  text "RoHS" at 10980.96,1523.39 h40
  text "OTHER" at 11625.36,1523.39 h40
  text "PER ORDER" at 12022.42,1523.39 h40
  text "ALL BOARDS MUST MEET OR EXCEED UL94-V0 REQUIREMENTS." at 9706,1369.57 h40
  text "PCB MUST BEAR THE UL94V-0 UL REGISTERED MATERIAL ID NUMBER" at 9706,1253.5 h40
  text "ADDITIONAL REQUIREMENTS:" at 9678.46,1084.08 h40
  text "MICROSECTION:" at 9753.23,976.95 h40
  text "YES" at 10658.96,976.95 h40
  text "REQUIRED" at 11520.46,832.62 h40
  text "BARE BOARD ELEC. TEST:" at 9753.23,829.76 h40
  text "NONE" at 11058.96,829.76 h40
  text "X" at 11402.46,829.76 h40
  text "PER ORDER" at 12112.46,829.76 h40
  text "XX MIL VIAS REQUIRE NON-CONDUCTIVE FILL AND PLANARIZE" at 9921.38,624.82 h40
  text "XX MIL VIAS REQUIRE CONDUCTIVE FILL AND PLANARIZE" at 9929.38,520.84 h40
  text "OUTER XX MIL VIAS REQUIRE 50 OHM SINGLE-ENDED IMPEDANCE" at 9928.39,357.46 h40
  text "LAYER 2 & 3 (INNER LAYERS) XX MIL WIDE, XX MIL SPACE / TRACES REQUIRE 100 OHM DIFFERENTIAL IMPEDANCE" at 9920.39,121.74 h40
  text ".Layer_Name" at -1078,-1628.49 h40
M11 Gerber Information:
  lines w10: -1947,-1700.17 4653,-1700.17 ; -1947,-1496.83 4655,-1496.83 ; -1947,-1293.5 -1947,-1903.5 2058,-1903.5 4655,-1903.5 4655,-1293.5 -1946.5,-1293.5 -1946.5,-1903.5 -371,-1903.5 ; 518,-1903.5 518,-1293.5 ; 1785,-1496.83 1785,-1293.5 ; 2625,-1496.83 2625,-1293.5 ; 3247,-1910 3247,-1707.17
  text "ALL ARTWORK VIEWED FROM TOP SIDE" at -1883.5,-1425.67 h40
  text "BOARD #:" at 593,-1425.67 h40
  text ".PRJ_Number" at 1138.5,-1425.67 h40
  text "REV:" at 1983,-1425.67 h40
  text ".PCB_Rev" at 2274.5,-1425.67 h40
  text "SVN REV:" at 2821,-1425.67 h40
  text ".VersionControl_RevNumber" at 3327,-1425.67 h40
  text "LAYER NAME =" at -1883.5,-1628.49 h40
  text "TID #:" at 593,-1629 h40
  text ".TID" at 1138.5,-1629 h40
  text "PLOT NAME =" at -1883.5,-1834.34 h40
  text ".plot_File_Name" at -1078,-1834.34 h40
  text "GENERATED    :" at 595,-1834.34 h40
  text ".Print_Date" at 1464.5,-1834.34 h40
  text ".Print_Time" at 2193.5,-1834.34 h40
  text "TEXAS INSTRUMENTS" at 3458,-1834.34 h40
M12 Stackup:
  drawing of 503 lines, arcs and shapes, not listed
  text "Layer" at 7587.05,6997.5 h40
  text "Name" at 7866.99,6997.5 h40
  text "Material" at 8500.15,6997.5 h40
  text "Thickness" at 9080,6997.5 h40
  text "Constant" at 9519.89,6997.5 h40
  text "Board Layer Stack" at 9906.46,6997.5 h40
  text "1" at 7587.05,6917.5 h40
  text "Top Overlay" at 7866.99,6917.5 h40
  text "2" at 7587.05,6837.5 h40
  text "Top Solder" at 7866.99,6837.5 h40
  text "Solder Resist" at 8500.15,6837.5 h40
  text "0.40mil" at 9080,6837.5 h40
  text "3.5" at 9519.89,6837.5 h40
  text "3" at 7587.05,6757.5 h40
  text "Top Layer" at 7866.99,6757.5 h40
  text "Copper" at 8500.15,6757.5 h40
  text "2.80mil" at 9080,6757.5 h40
  text "4" at 7587.05,6677.5 h40
  text "Dielectric1" at 7866.99,6677.5 h40
  text "FR-4" at 8500.15,6677.5 h40
  text "5.50mil" at 9080,6677.5 h40
  text "4.8" at 9519.89,6677.5 h40
  text "5" at 7587.05,6597.5 h40
  text "Signal Layer 1" at 7866.99,6597.5 h40
  text "Copper" at 8500.15,6597.5 h40
  text "2.80mil" at 9080,6597.5 h40
  text "6" at 7587.05,6517.5 h40
  text "Dielectric 2" at 7866.99,6517.5 h40
  text "5.50mil" at 9080,6517.5 h40
  text "4.2" at 9519.89,6517.5 h40
  text "7" at 7587.05,6437.5 h40
  text "Signal Layer 2" at 7866.99,6437.5 h40
  text "Copper" at 8500.15,6437.5 h40
  text "2.80mil" at 9080,6437.5 h40
  text "8" at 7587.05,6357.5 h40
  text "Dielectric 3" at 7866.99,6357.5 h40
  text "5.50mil" at 9080,6357.5 h40
  text "4.2" at 9519.89,6357.5 h40
  text "9" at 7587.05,6277.5 h40
  text "Signal Layer 3" at 7866.99,6277.5 h40
  text "Copper" at 8500.15,6277.5 h40
  text "2.80mil" at 9080,6277.5 h40
  text "10" at 7587.05,6197.5 h40
  text "Dielectric 4" at 7866.99,6197.5 h40
  text "5.50mil" at 9080,6197.5 h40
  text "4.2" at 9519.89,6197.5 h40
  text "11" at 7587.05,6117.5 h40
  text "Signal Layer 4" at 7866.99,6117.5 h40
  text "Copper" at 8500.15,6117.5 h40
  text "2.80mil" at 9080,6117.5 h40
  text "12" at 7587.05,6037.5 h40
  text "Dielectric 5" at 7866.99,6037.5 h40
  text "5.50mil" at 9080,6037.5 h40
  text "4.2" at 9519.89,6037.5 h40
  text "13" at 7587.05,5957.5 h40
  text "Signal Layer 5" at 7866.99,5957.5 h40
  text "Copper" at 8500.15,5957.5 h40
  text "2.80mil" at 9080,5957.5 h40
  text "14" at 7587.05,5877.5 h40
  text "Dielectric 6" at 7866.99,5877.5 h40
  text "5.50mil" at 9080,5877.5 h40
  text "4.2" at 9519.89,5877.5 h40
  text "15" at 7587.05,5797.5 h40
  text "Signal Layer 6" at 7866.99,5797.5 h40
  text "Copper" at 8500.15,5797.5 h40
  text "2.80mil" at 9080,5797.5 h40
  text "16" at 7587.05,5717.5 h40
  text "Dielectric 7" at 7866.99,5717.5 h40
  text "5.50mil" at 9080,5717.5 h40
  text "4.2" at 9519.89,5717.5 h40
  text "17" at 7587.05,5637.5 h40
  text "Bottom Layer" at 7866.99,5637.5 h40
  text "Copper" at 8500.15,5637.5 h40
  text "2.80mil" at 9080,5637.5 h40
  text "18" at 7587.05,5557.5 h40
  text "Bottom Solder" at 7866.99,5557.5 h40
  text "Solder Resist" at 8500.15,5557.5 h40
  text "0.40mil" at 9080,5557.5 h40
  text "3.5" at 9519.89,5557.5 h40
  text "19" at 7587.05,5477.5 h40
  text "Bottom Overlay" at 7866.99,5477.5 h40
  text ".Layer_Name" at -1078,-1628.49 h40
M13 Component Bodies Top:
  text ".Layer_Name" at -1078,-1628.49 h40
M14 Component Bodies Bottom:
  text ".Layer_Name" at -1078,-1628.49 h40
M15 Courtyards Top:
  text ".Layer_Name" at -1078,-1628.49 h40
M16 Courtyards Bottom:
  text ".Layer_Name" at -1078,-1628.49 h40
Drill Drawing:
  lines w10: 6206.65,3304.56 6250.79,3304.56 6250.79,3348.7 6206.65,3348.7 6206.65,3304.56 ; 6206.65,3414.91 6217.68,3414.91 6228.72,3403.88 6239.75,3414.91 6250.79,3414.91 6239.75,3425.95 6250.79,3436.98 6239.75,3436.98 6228.72,3448.02 6217.68,3436.98 6206.65,3436.98 6217.68,3425.95 6206.65,3414.91 ; 6206.65,3525.27 6228.72,3503.2 6250.79,3525.27 6228.72,3547.34 6206.65,3525.27 ; 6206.65,3602.52 6228.72,3613.55 6250.79,3602.52 6239.75,3624.59 6250.79,3646.66 6228.72,3635.62 6206.65,3646.66 6217.68,3624.59 6206.65,3602.52 ; 6206.65,3701.84 6206.65,3712.87 6217.68,3723.91 6206.65,3734.94 6206.65,3745.98 6217.68,3745.98 6228.72,3734.94 6239.75,3745.98 6250.79,3745.98 6250.79,3734.94 6239.75,3723.91 6250.79,3712.87 6250.79,3701.84 6239.75,3701.84 6228.72,3712.87 6217.68,3701.84 6206.65,3701.84 ; 6206.65,3812.19 6217.68,3812.19 6217.68,3801.16 6239.75,3801.16 6239.75,3812.19 6250.79,3812.19 6250.79,3834.26 6239.75,3834.26 6239.75,3845.3 6217.68,3845.3 6217.68,3834.26 6206.65,3834.26 6206.65,3812.19
  lines w12: 6166,3274.76 9277.21,3274.76 ; 6166,3870.68 9277.21,3870.68 ; 6481.49,3175.44 6481.49,3970 ; 6798.58,3175.44 6798.58,3970 ; 7420.22,3175.44 7420.22,3970 ; 7664.41,3175.44 7664.41,3970 ; 8024.66,3175.44 8024.66,3970 ; 8733.12,3175.44 8733.12,3970 ; 6166,3175.44 9277.21,3175.44 9277.21,3970 6166,3970 6166,3175.44
  text "Symbol" at 6225.59,3900.48 h72
  text "Quantity" at 6511.28,3900.48 h72
  text "Finished Hole Size" at 6828.38,3900.48 h72
  text "Plated" at 7450.02,3900.48 h72
  text "Hole Type" at 7694.21,3900.48 h72
  text "Drill Layer Pair" at 8054.45,3900.48 h72
  text "Hole Tolerance" at 8762.92,3900.48 h72
  text "68" at 6511.28,3801.16 h60
  text "7.87mil (0.200mm)" at 6828.38,3801.16 h60
  text "PTH" at 7450.02,3801.16 h60
  text "Round" at 7694.21,3801.16 h60
  text "Top Layer - Bottom Layer" at 8054.45,3801.16 h60
  text "1028" at 6511.28,3701.84 h60
  text "10.00mil (0.254mm)" at 6828.38,3701.84 h60
  text "PTH" at 7450.02,3701.84 h60
  text "Round" at 7694.21,3701.84 h60
  text "Top Layer - Bottom Layer" at 8054.45,3701.84 h60
  text "251" at 6511.28,3602.52 h60
  text "16.00mil (0.406mm)" at 6828.38,3602.52 h60
  text "PTH" at 7450.02,3602.52 h60
  text "Round" at 7694.21,3602.52 h60
  text "Top Layer - Bottom Layer" at 8054.45,3602.52 h60
  text "2" at 6511.28,3503.2 h60
  text "20.00mil (0.508mm)" at 6828.38,3503.2 h60
  text "PTH" at 7450.02,3503.2 h60
  text "Round" at 7694.21,3503.2 h60
  text "Top Layer - Bottom Layer" at 8054.45,3503.2 h60
  text "21" at 6511.28,3403.88 h60
  text "35.43mil (0.900mm)" at 6828.38,3403.88 h60
  text "PTH" at 7450.02,3403.88 h60
  text "Round" at 7694.21,3403.88 h60
  text "Top Layer - Bottom Layer" at 8054.45,3403.88 h60
  text "4" at 6511.28,3304.56 h60
  text "270.00mil (6.858mm)" at 6828.38,3304.56 h60
  text "PTH" at 7450.02,3304.56 h60
  text "Round" at 7694.21,3304.56 h60
  text "Top Layer - Bottom Layer" at 8054.45,3304.56 h60
  text "1374 Total" at 6511.28,3205.24 h60
  text ".Layer_Name" at -1078,-1628.49 h40
M17 Embedded Cavity:
  text ".Layer_Name" at -1078,-1628.49 h40
M18 Embedded Assembly:
  text ".Layer_Name" at -1078,-1628.49 h40
M19 Embedded Keepout:
  text ".Layer_Name" at -1078,-1628.49 h40

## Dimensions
0,-85 to 5643.75,-190 on M2 Board Dimensions
345,4583.04 to 890.99,-2.87 on M2 Board Dimensions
